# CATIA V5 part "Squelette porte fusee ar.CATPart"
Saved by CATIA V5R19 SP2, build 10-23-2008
Part number: Squelette porte fusée ar
Bounding box of the stored display mesh (mm): x 316.227 to 336.227, y -42.912 to -20.23, z 61.355 to 96.874
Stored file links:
  D:\Mes Documents\ressource\CATIA\Ensemble Catia\Voiture_Telecommmande\SchemaCinematiqueFinal\Squelette porte fusee ar.CATPart
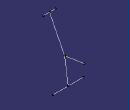
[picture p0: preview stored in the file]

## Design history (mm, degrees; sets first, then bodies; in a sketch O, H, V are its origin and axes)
AxisSystem1: origin (0, 0, 0), X (1, 0, 0), Y (0, 1, 0), Z (0, 0, 1)
Body1 (main body)
  Line1 to Line3: stored without definition
  Point1 to Point3: stored without definition
  Line4: stored without definition
  Line5: stored without definition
